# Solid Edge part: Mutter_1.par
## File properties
Sűrűség: 0,000 kg/m^3
Pontosság: 0,990
Author: ahadarics
Last saved by: ahadarics
Revision: 76
Username: ahadarics
Dokumentum tartalom típus: 0
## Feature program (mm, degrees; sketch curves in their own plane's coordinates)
base feature "unnamed BaseFeature 1"
thread "unnamed Thread 1"
chamfer "Letörés_1"  SetBackValue2 = 60 deg
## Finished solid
Body 1: solid body, 23 faces, 46 edges, 24 vertices.
  Faces by surface: cone 14, plane 8, cylinder 1
  Edges by curve: spline 24, circle 16, line 6
Bounding box of the edges (mm): 5.000 x 15.011 x 13.000, from (0, -7.5056, -6.5) to (5, 7.5056, 6.5).
Cylindrical faces by radius (mm): R3.3235 x1
Conical faces (half-angle, radius in mm at the cone's reference point): 60 deg R3.3235 x1, 60 deg R4.0163 x1, 60 deg R7.0028 x12
Planar faces by outward normal: +x 1, +z 1, -x 1, -z 1, oblique 4
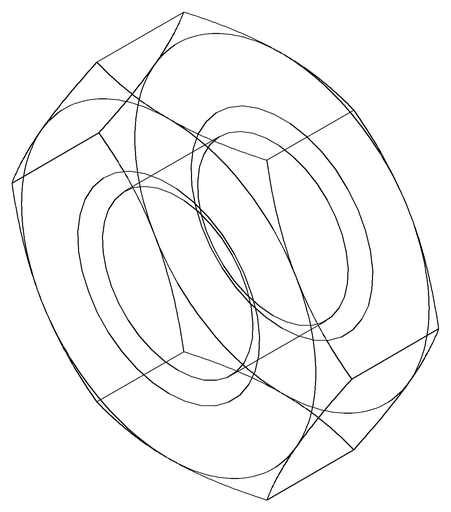
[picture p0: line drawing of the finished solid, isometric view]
